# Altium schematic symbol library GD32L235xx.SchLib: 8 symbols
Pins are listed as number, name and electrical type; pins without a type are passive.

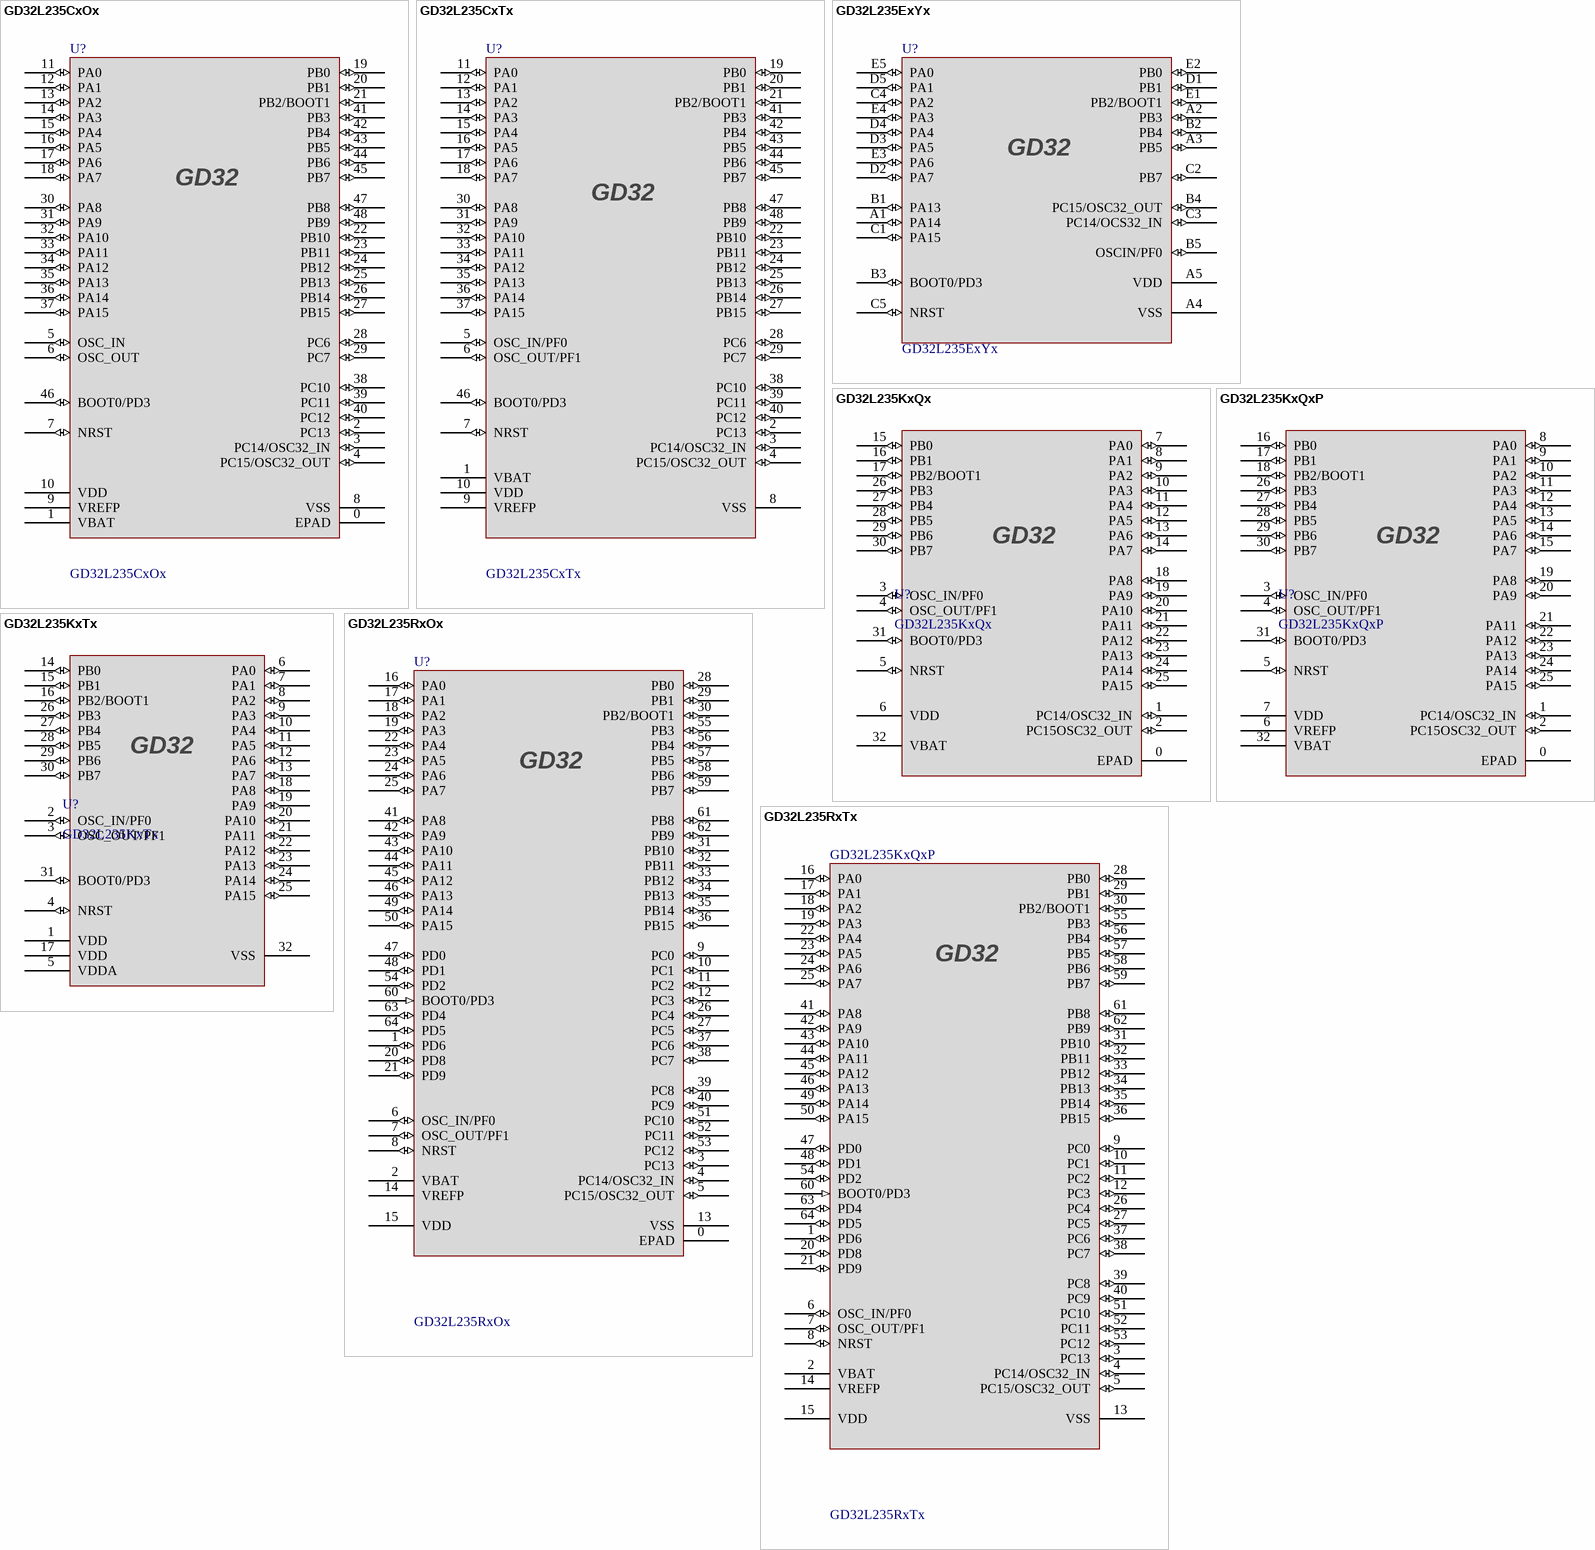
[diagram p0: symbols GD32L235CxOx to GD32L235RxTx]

## GD32L235CxOx
designator U?
footprint QFN48_5X5X0.6
pins: 0 EPAD (power), 1 VBAT (power), 2 PC13 (io), 3 PC14/OSC32_IN (io), 4 PC15/OSC32_OUT (io), 5 OSC_IN (io), 6 OSC_OUT (io), 7 NRST (io), 8 VSS (power), 9 VREFP (power), 10 VDD (power), 11 PA0 (io), 12 PA1 (io), 13 PA2 (io), 14 PA3 (io), 15 PA4 (io), 16 PA5 (io), 17 PA6 (io), 18 PA7 (io), 19 PB0 (io), 20 PB1 (io), 21 PB2/BOOT1 (io), 22 PB10 (io), 23 PB11 (io), 24 PB12 (io), 25 PB13 (io), 26 PB14 (io), 27 PB15 (io), 28 PC6 (io), 29 PC7 (io), 30 PA8 (io), 31 PA9 (io), 32 PA10 (io), 33 PA11 (io), 34 PA12 (io), 35 PA13 (io), 36 PA14 (io), 37 PA15 (io), 38 PC10 (io), 39 PC11 (io), 40 PC12 (io), 41 PB3 (io), 42 PB4 (io), 43 PB5 (io), 44 PB6 (io), 45 PB7 (io), 46 BOOT0/PD3 (io), 47 PB8 (io), 48 PB9 (io)

## GD32L235CxTx
designator U?
footprint LQFP48_7x7x1.6
pins: 1 VBAT (power), 2 PC13 (io), 3 PC14/OSC32_IN (io), 4 PC15/OSC32_OUT (io), 5 OSC_IN/PF0 (io), 6 OSC_OUT/PF1 (io), 7 NRST (io), 8 VSS (power), 9 VREFP (power), 10 VDD (power), 11 PA0 (io), 12 PA1 (io), 13 PA2 (io), 14 PA3 (io), 15 PA4 (io), 16 PA5 (io), 17 PA6 (io), 18 PA7 (io), 19 PB0 (io), 20 PB1 (io), 21 PB2/BOOT1 (io), 22 PB10 (io), 23 PB11 (io), 24 PB12 (io), 25 PB13 (io), 26 PB14 (io), 27 PB15 (io), 28 PC6 (io), 29 PC7 (io), 30 PA8 (io), 31 PA9 (io), 32 PA10 (io), 33 PA11 (io), 34 PA12 (io), 35 PA13 (io), 36 PA14 (io), 37 PA15 (io), 38 PC10 (io), 39 PC11 (io), 40 PC12 (io), 41 PB3 (io), 42 PB4 (io), 43 PB5 (io), 44 PB6 (io), 45 PB7 (io), 46 BOOT0/PD3 (io), 47 PB8 (io), 48 PB9 (io)

## GD32L235ExYx
designator U?
footprint WLCSP25_2.092x1.975x0.5
pins: A1 PA14 (io), A2 PB3 (io), A3 PB5 (io), A4 VSS (power), A5 VDD (power), B1 PA13 (io), B2 PB4 (io), B3 BOOT0/PD3 (io), B4 PC15/OSC32_OUT (io), B5 OSCIN/PF0 (io), C1 PA15 (io), C2 PB7 (io), C3 PC14/OCS32_IN (io), C4 PA2 (io), C5 NRST (io), D1 PB1 (io), D2 PA7 (io), D3 PA5 (io), D4 PA4 (io), D5 PA1 (io), E1 PB2/BOOT1 (io), E2 PB0 (io), E3 PA6 (io), E4 PA3 (io), E5 PA0 (io)
2 alternate drawings of the same symbol

## GD32L235KxQx
designator U?
footprint QFN32_4x4x0.8
pins: 0 EPAD (power), 1 PC14/OSC32_IN (io), 2 PC15OSC32_OUT (io), 3 OSC_IN/PF0 (io), 4 OSC_OUT/PF1 (io), 5 NRST (io), 6 VDD (power), 7 PA0 (io), 8 PA1 (io), 9 PA2 (io), 10 PA3 (io), 11 PA4 (io), 12 PA5 (io), 13 PA6 (io), 14 PA7 (io), 15 PB0 (io), 16 PB1 (io), 17 PB2/BOOT1 (io), 18 PA8 (io), 19 PA9 (io), 20 PA10 (io), 21 PA11 (io), 22 PA12 (io), 23 PA13 (io), 24 PA14 (io), 25 PA15 (io), 26 PB3 (io), 27 PB4 (io), 28 PB5 (io), 29 PB6 (io), 30 PB7 (io), 31 BOOT0/PD3 (io), 32 VBAT (power)

## GD32L235KxQxP
designator U?
footprint QFN32_4x4x0.8
pins: 0 EPAD (power), 1 PC14/OSC32_IN (io), 2 PC15OSC32_OUT (io), 3 OSC_IN/PF0 (io), 4 OSC_OUT/PF1 (io), 5 NRST (io), 6 VREFP, 7 VDD (power), 8 PA0 (io), 9 PA1 (io), 10 PA2 (io), 11 PA3 (io), 12 PA4 (io), 13 PA5 (io), 14 PA6 (io), 15 PA7 (io), 16 PB0 (io), 17 PB1 (io), 18 PB2/BOOT1 (io), 19 PA8 (io), 20 PA9 (io), 21 PA11 (io), 22 PA12 (io), 23 PA13 (io), 24 PA14 (io), 25 PA15 (io), 26 PB3 (io), 27 PB4 (io), 28 PB5 (io), 29 PB6 (io), 30 PB7 (io), 31 BOOT0/PD3 (io), 32 VBAT (power)

## GD32L235KxTx
designator U?
footprint LQFP32_7x7X1.6
pins: 1 VDD (power), 2 OSC_IN/PF0 (io), 3 OSC_OUT/PF1 (io), 4 NRST (io), 5 VDDA (power), 6 PA0 (io), 7 PA1 (io), 8 PA2 (io), 9 PA3 (io), 10 PA4 (io), 11 PA5 (io), 12 PA6 (io), 13 PA7 (io), 14 PB0 (io), 15 PB1 (io), 16 PB2/BOOT1 (io), 17 VDD (power), 18 PA8 (io), 19 PA9 (io), 20 PA10 (io), 21 PA11 (io), 22 PA12 (io), 23 PA13 (io), 24 PA14 (io), 25 PA15 (io), 26 PB3 (io), 27 PB4 (io), 28 PB5 (io), 29 PB6 (io), 30 PB7 (io), 31 BOOT0/PD3 (io), 32 VSS (power)

## GD32L235RxOx
designator U?
footprint QFN64_7X7X0.8
pins: 0 EPAD (power), 1 PD6 (io), 2 VBAT (power), 3 PC13 (io), 4 PC14/OSC32_IN (io), 5 PC15/OSC32_OUT (io), 6 OSC_IN/PF0 (io), 7 OSC_OUT/PF1 (io), 8 NRST (io), 9 PC0 (io), 10 PC1 (io), 11 PC2 (io), 12 PC3 (io), 13 VSS (power), 14 VREFP (power), 15 VDD (power), 16 PA0 (io), 17 PA1 (io), 18 PA2 (io), 19 PA3 (io), 20 PD8 (io), 21 PD9 (io), 22 PA4 (io), 23 PA5 (io), 24 PA6 (io), 25 PA7 (io), 26 PC4 (io), 27 PC5 (io), 28 PB0 (io), 29 PB1 (io), 30 PB2/BOOT1 (io), 31 PB10 (io), 32 PB11 (io), 33 PB12 (io), 34 PB13 (io), 35 PB14 (io), 36 PB15 (io), 37 PC6 (io), 38 PC7 (io), 39 PC8 (io), 40 PC9 (io), 41 PA8 (io), 42 PA9 (io), 43 PA10 (io), 44 PA11 (io), 45 PA12 (io), 46 PA13 (io), 47 PD0 (io), 48 PD1 (io), 49 PA14 (io), 50 PA15 (io), 51 PC10 (io), 52 PC11 (io), 53 PC12 (io), 54 PD2 (io), 55 PB3 (io), 56 PB4 (io), 57 PB5 (io), 58 PB6 (io), 59 PB7 (io), 60 BOOT0/PD3 (in), 61 PB8 (io), 62 PB9 (io), 63 PD4 (io), 64 PD5 (io)

## GD32L235RxTx
designator GD32L235KxQxP
footprint LQPF64_10x10x1.6
pins: 1 PD6 (io), 2 VBAT (power), 3 PC13 (io), 4 PC14/OSC32_IN (io), 5 PC15/OSC32_OUT (io), 6 OSC_IN/PF0 (io), 7 OSC_OUT/PF1 (io), 8 NRST (io), 9 PC0 (io), 10 PC1 (io), 11 PC2 (io), 12 PC3 (io), 13 VSS (power), 14 VREFP (power), 15 VDD (power), 16 PA0 (io), 17 PA1 (io), 18 PA2 (io), 19 PA3 (io), 20 PD8 (io), 21 PD9 (io), 22 PA4 (io), 23 PA5 (io), 24 PA6 (io), 25 PA7 (io), 26 PC4 (io), 27 PC5 (io), 28 PB0 (io), 29 PB1 (io), 30 PB2/BOOT1 (io), 31 PB10 (io), 32 PB11 (io), 33 PB12 (io), 34 PB13 (io), 35 PB14 (io), 36 PB15 (io), 37 PC6 (io), 38 PC7 (io), 39 PC8 (io), 40 PC9 (io), 41 PA8 (io), 42 PA9 (io), 43 PA10 (io), 44 PA11 (io), 45 PA12 (io), 46 PA13 (io), 47 PD0 (io), 48 PD1 (io), 49 PA14 (io), 50 PA15 (io), 51 PC10 (io), 52 PC11 (io), 53 PC12 (io), 54 PD2 (io), 55 PB3 (io), 56 PB4 (io), 57 PB5 (io), 58 PB6 (io), 59 PB7 (io), 60 BOOT0/PD3 (in), 61 PB8 (io), 62 PB9 (io), 63 PD4 (io), 64 PD5 (io)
